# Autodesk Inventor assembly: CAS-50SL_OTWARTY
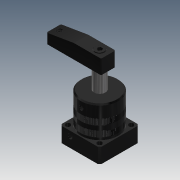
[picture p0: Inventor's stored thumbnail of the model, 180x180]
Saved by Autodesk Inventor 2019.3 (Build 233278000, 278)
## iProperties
Created: 2009-09
Part Number: CAS-50SL_OTWARTY
Material: Ogólny
Document SubType Name: Assembly
Designer: CADENGINEERING4
Sending System: PRO/ENGINEER BY PARAMETRIC TECHNOLOGY CORPORATION, 2007170
Preprocessor: PRO/ENGINEER BY PARAMETRIC TECHNOLOGY CORPORATION, 2007170
Title: CAS-50S_ASM
Author: Administrator
Revision Number: 1LAST_VERSION
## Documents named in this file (7)
- D:\Vault_2016\Projekty\STRONA\Pneumatic\Line ; Pipe connecct - type\cas-50s_asm\CAS-50SL_OTWARTY.iam
- D:\Vault_2016\Projekty\STRONA\Pneumatic\Line ; Pipe connecct - type\cas-50s_asm\CAS-50BT.ipt
- D:\Vault_2016\Projekty\STRONA\Pneumatic\Line ; Pipe connecct - type\cas-50s_asm\CAS-50SHSG.ipt
- D:\Vault_2016\Projekty\STRONA\Pneumatic\Line ; Pipe connecct - type\cas-50s_asm\CAS-50HG.ipt
- D:\Vault_2016\Projekty\STRONA\Pneumatic\Line ; Pipe connecct - type\cas-50s_asm\M4.ipt
- D:\Vault_2016\Projekty\STRONA\Pneumatic\Line ; Pipe connecct - type\cas-50s_asm\CAS-50SYB.ipt
- D:\Vault_2016\Projekty\STRONA\Pneumatic\Line ; Pipe connecct - type\cas-50s_asm\M10LC.ipt
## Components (9 placed, 9 different names)
1. CAS-50BT_0
2. CAS-50SHSG_1
3. CAS-50HG_2
4. M4_3
5. M4_4
6. M4_5
7. M4_6
8. CAS-50SYB_7
9. M10LC_8
